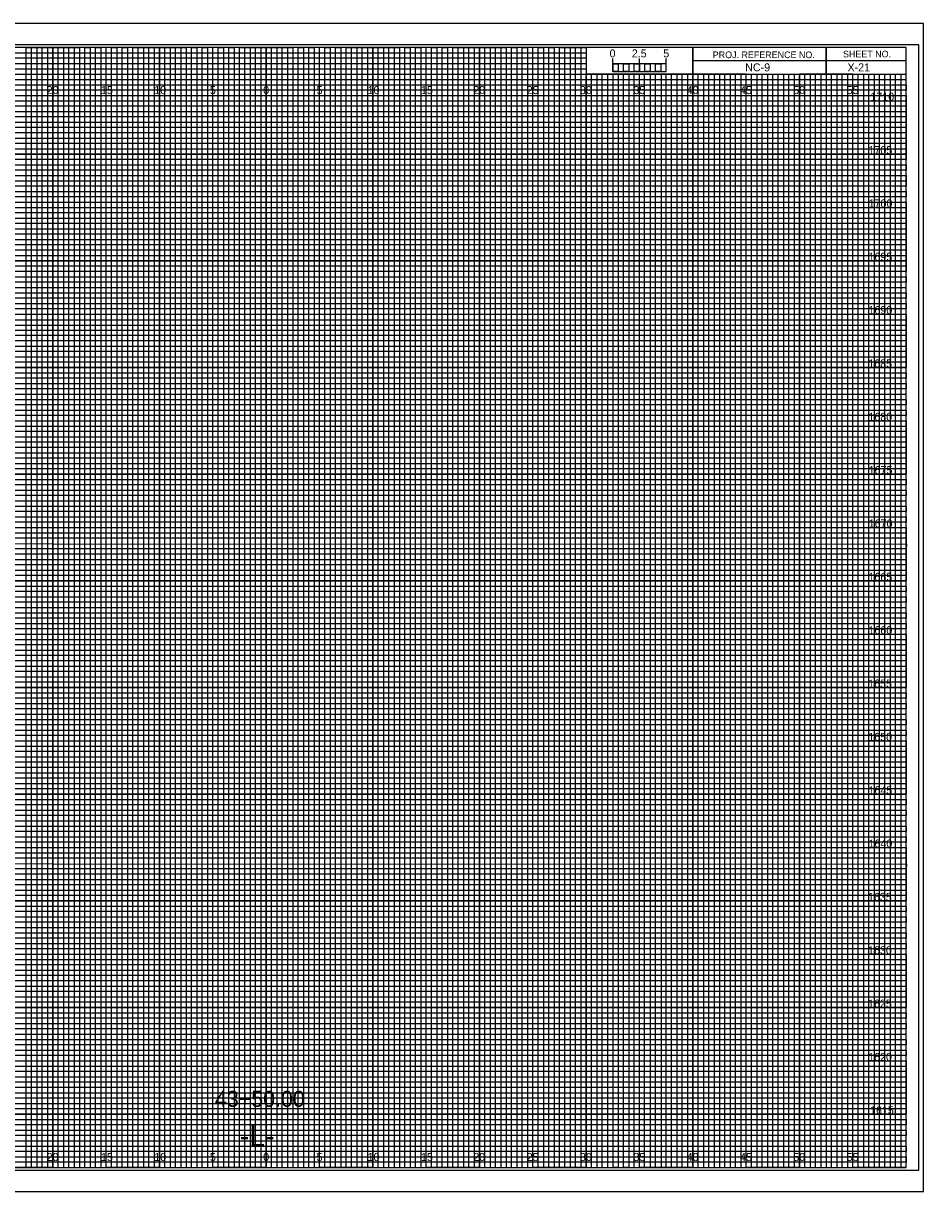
# Model space of a CAD drawing. Extents: x -8289 to 162, y -2 to 23207.
# Drawn here: x 77.2 to 161.7, y 2087.8 to 2197.2 of the extents above; entities that cross this region are included whole.
import ezdxf

# ---------------------------------------------------------------- set-up
doc = ezdxf.new("R2010")
doc.units = 0
for name, color, linetype in [('Prop XS Alignment Label', 7, 'Continuous'), ('Prop XS Bar Scale Labels', 7, 'Continuous'), ('Prop XS Elevation Labels', 7, 'Continuous'), ('Prop XS Offset Labels', 7, 'Continuous'), ('Prop XS Project Number', 7, 'Continuous'), ('Prop XS Sheet Number', 7, 'Continuous'), ('Prop XS Station Labels', 7, 'Continuous'), ('Sheet Cross Section CELL', 7, 'Continuous'), ('Sheet Cross Section Grid Major CELL', 7, 'Continuous'), ('Sheet Cross Section Grid Middle CELL', 7, 'Continuous'), ('Sheet Cross Section Grid Minor 1 CELL', 7, 'Continuous'), ('Sheet Cross Section Grid Minor 2 CELL', 7, 'Continuous'), ('Sheet Cross Section Scale CELL', 7, 'Continuous'), ('Sheet Cutting Line CELL', 7, 'Continuous'), ('Sheet DOT Grid CELL', 7, 'Continuous'), ('Sheet Plot Border Inside CELL', 7, 'Continuous'), ('Sheet Plot Border Outside CELL', 7, 'Continuous')]:
    doc.layers.add(name, color=color, linetype=linetype)

msp = doc.modelspace()

# ---------------------------------------------------------------- linework, layer by layer
at = {"layer": 'Sheet Cross Section CELL'}
for p, q in [((152.5, 2195), (152.5, 2192.5)), ((152.5, 2192.5), (152.5, 2195)), ((140, 2193.75), (140, 2192.5)), ((160, 2193.74), (140, 2193.74)), ((140, 2192.5), (160, 2192.5))]:
    msp.add_line(p, q, dxfattribs=at)
for points in [[(160, 2195), (0, 2195), (0, 2090), (160, 2090)], [(140, 2195), (130, 2195), (130, 2192.51), (140, 2192.51)], [(160, 2195), (140, 2195), (140, 2192.5), (160, 2192.5)]]:
    msp.add_lwpolyline(points, close=True, dxfattribs=at)
at = {"layer": 'Sheet Cross Section Grid Major CELL'}
for p, q in [((85, 2195), (80, 2195)), ((80, 2195), (80, 2090)), ((85, 2090), (85, 2195)), ((95, 2195), (90, 2195)), ((90, 2195), (90, 2090)), ((95, 2090), (95, 2195)), ((105, 2195), (100, 2195)), ((100, 2195), (100, 2090)), ((105, 2090), (105, 2195)), ((115, 2195), (110, 2195)), ((110, 2195), (110, 2090)), ((115, 2090), (115, 2195)), ((125, 2195), (120, 2195)), ((120, 2195), (120, 2090)), ((125, 2090), (125, 2195)), ((130, 2195), (130, 2090)), ((135, 2090), (135, 2192.5)), ((145, 2192.5), (140, 2192.5)), ((140, 2192.5), (140, 2090)), ((145, 2090), (145, 2192.5)), ((155, 2192.5), (150, 2192.5)), ((150, 2192.5), (150, 2090)), ((155, 2090), (155, 2192.5)), ((80, 2090), (75, 2090)), ((90, 2090), (85, 2090)), ((100, 2090), (95, 2090)), ((110, 2090), (105, 2090)), ((120, 2090), (115, 2090)), ((130, 2090), (125, 2090)), ((140, 2090), (135, 2090)), ((150, 2090), (145, 2090)), ((160, 2090), (155, 2090)), ((160, 2090), (160, 2090))]:
    msp.add_line(p, q, dxfattribs=at)
for points in [[(0, 2190), (160, 2190), (160, 2185), (0, 2185)], [(0, 2180), (160, 2180), (160, 2175), (0, 2175)], [(0, 2170), (160, 2170), (160, 2165), (0, 2165)], [(0, 2160), (160, 2160), (160, 2155), (0, 2155)], [(0, 2150), (160, 2150), (160, 2145), (0, 2145)], [(0, 2140), (160, 2140), (160, 2135), (0, 2135)], [(0, 2130), (160, 2130), (160, 2125), (0, 2125)], [(0, 2120), (160, 2120), (160, 2115), (0, 2115)], [(0, 2110), (160, 2110), (160, 2105), (0, 2105)], [(0, 2100), (160, 2100), (160, 2095), (0, 2095)]]:
    msp.add_lwpolyline(points, dxfattribs=at)
at = {"layer": 'Sheet Cross Section Grid Middle CELL'}
for points in [[(72.5, 2090), (77.5, 2090), (77.5, 2195), (82.5, 2195), (82.5, 2090), (87.5, 2090), (87.5, 2195), (92.5, 2195), (92.5, 2090), (97.5, 2090), (97.5, 2195), (102.5, 2195), (102.5, 2090), (107.5, 2090), (107.5, 2195), (112.5, 2195), (112.5, 2090), (117.5, 2090), (117.5, 2195), (122.5, 2195), (122.5, 2090), (127.5, 2090), (127.5, 2195), (129.97, 2195), (130, 2195), (130, 2192.5), (132.5, 2192.5), (132.5, 2090), (137.5, 2090), (137.5, 2192.5), (142.5, 2192.5), (142.5, 2090), (147.5, 2090), (147.5, 2192.5), (152.5, 2192.5), (152.5, 2090), (157.5, 2090), (157.5, 2192.5)], [(0, 2192.5), (137.5, 2192.5)], [(0, 2182.5), (160, 2182.5), (160, 2187.5), (0, 2187.5)], [(0, 2172.5), (160, 2172.5), (160, 2177.5), (0, 2177.5)], [(0, 2162.5), (160, 2162.5), (160, 2167.5), (0, 2167.5)], [(0, 2152.5), (160, 2152.5), (160, 2157.5), (0, 2157.5)], [(0, 2142.5), (160, 2142.5), (160, 2147.5), (0, 2147.5)], [(0, 2132.5), (160, 2132.5), (160, 2137.5), (0, 2137.5)], [(0, 2122.5), (160, 2122.5), (160, 2127.5), (0, 2127.5)], [(0, 2112.5), (160, 2112.5), (160, 2117.5), (0, 2117.5)], [(0, 2102.5), (160, 2102.5), (160, 2107.5), (0, 2107.5)], [(0, 2092.5), (160, 2092.5), (160, 2097.5), (0, 2097.5)]]:
    msp.add_lwpolyline(points, dxfattribs=at)
at = {"layer": 'Sheet Cross Section Grid Minor 1 CELL'}
for p, q in [((0, 2194.5), (130, 2194.5)), ((130, 2194.5), (130, 2193.99)), ((130, 2193.99), (0, 2193.99)), ((0, 2193.5), (130, 2193.5)), ((130, 2193.5), (130, 2192.95)), ((130, 2192.95), (0, 2192.95)), ((0, 2192), (160, 2192))]:
    msp.add_line(p, q, dxfattribs=at)
for points in [[(0, 2191.5), (135, 2191.5), (160, 2191.5), (160, 2191), (0, 2191)], [(0, 2190.5), (160, 2190.5), (160, 2189.5), (0, 2189.5)], [(0, 2189), (160, 2189), (160, 2188.5), (0, 2188.49)], [(0, 2188), (160, 2188), (160, 2187), (0, 2187)], [(0, 2186.5), (160, 2186.5), (160, 2186), (0, 2186)], [(0, 2185.5), (160, 2185.5), (160, 2184.5), (0, 2184.5)], [(0, 2184), (160, 2184), (160, 2183.5), (0, 2183.5)], [(0, 2183), (160, 2183), (160, 2182), (0, 2182)], [(0, 2181.5), (160, 2181.5), (160, 2181), (0, 2181)], [(0, 2180.5), (160, 2180.5), (160, 2179.5), (0, 2179.5)], [(0, 2179), (160, 2179), (160, 2178.5), (0, 2178.5)], [(0, 2178), (160, 2178), (160, 2176.97), (160, 2176.5), (160, 2176), (0, 2176)], [(0, 2177), (160, 2177), (160, 2176.5), (0, 2176.5)], [(0, 2175.5), (160, 2175.5), (160, 2174.5), (0, 2174.51)], [(0, 2174.51), (160, 2174.5), (160, 2174), (0, 2174)], [(0, 2173.5), (160, 2173.5), (160, 2173), (0, 2173)], [(0, 2172), (160, 2172), (160, 2171.5), (0, 2171.5)], [(0, 2171), (160, 2171), (160, 2170.5), (0, 2170.5)], [(-0.04, 2169.45), (160, 2169.45), (160, 2168.94), (-0.04, 2168.94)], [(0, 2168.5), (160, 2168.5), (160, 2168), (0, 2168)], [(0, 2167), (160, 2167), (160, 2166.5), (0, 2166.5)], [(0, 2166), (160, 2166), (160, 2165.5), (0, 2165.5)], [(0, 2164.5), (160, 2164.5), (160, 2164), (0, 2164)], [(0, 2163.5), (160, 2163.5), (160, 2163), (0, 2163)], [(0, 2162), (160, 2162), (160, 2161.5), (0, 2161.5)], [(0, 2161), (160, 2161), (160, 2160.5), (0, 2160.5)], [(0, 2159.5), (160, 2159.5), (160, 2158.99), (0, 2159)], [(0, 2158.5), (160, 2158.5), (160, 2158), (0, 2158)], [(0, 2157), (160, 2157), (160, 2156.5), (0, 2156.5)], [(0, 2156), (160, 2156), (160, 2155.5), (0, 2155.5)], [(0, 2154.5), (160, 2154.5), (160, 2154), (0, 2154)], [(0, 2153.5), (160, 2153.5), (160, 2153), (0, 2153)], [(0, 2152), (160, 2152), (160, 2151.5), (0, 2151.5)], [(0, 2151), (160, 2151), (160, 2150.5), (0, 2150.5)], [(0, 2149.5), (160, 2149.5), (160, 2149), (0, 2149)], [(0, 2148.49), (160.03, 2148.45), (160, 2148), (0, 2148)], [(0, 2147), (160, 2147), (160, 2146.5), (0, 2146.5)], [(0, 2146), (160, 2146), (160, 2145.5), (0, 2145.5)], [(0, 2144.5), (160, 2144.5), (160, 2144), (0, 2144)], [(0, 2143.5), (160, 2143.5), (160, 2143), (0, 2143)], [(0, 2142), (160, 2142), (160, 2141.5), (0, 2141.5)], [(0, 2141), (160, 2141), (160, 2140.5), (0, 2140.5)], [(0, 2139.5), (160, 2139.5), (160, 2139), (0, 2139)], [(0, 2138.5), (160, 2138.5), (160, 2138), (0, 2138)], [(0, 2137), (160, 2137), (160, 2136.5), (0, 2136.5)], [(0, 2136), (160, 2136), (160, 2135.5), (0, 2135.5)], [(0, 2134.5), (160, 2134.5), (160, 2134), (0, 2134)], [(0, 2133.5), (160, 2133.5), (160, 2133), (0, 2133)], [(0, 2132), (160, 2132), (160, 2131.5), (0, 2131.5)], [(0, 2131), (160, 2131), (160, 2130.5), (0, 2130.5)], [(0, 2129.5), (160, 2129.5), (160, 2128.99), (0, 2129)], [(0, 2128.5), (160, 2128.5), (160, 2128), (0, 2128)], [(0, 2127), (160, 2127), (160, 2126.5), (0, 2126.5)], [(0, 2126), (160, 2126), (160, 2125.5), (0, 2125.5)], [(0, 2124.5), (160, 2124.5), (160, 2124), (0, 2124)], [(0, 2123.5), (160, 2123.5), (160, 2123), (0, 2123)], [(0, 2122), (160, 2122), (160, 2121.5), (0, 2121.5)], [(0, 2121), (160, 2121), (160, 2120.5), (0, 2120.5)], [(0, 2119.5), (160, 2119.5), (160, 2119), (0, 2119)], [(0, 2118.49), (160.03, 2118.45), (160, 2118), (0, 2118)], [(0, 2117), (160, 2117), (160, 2116.5), (0, 2116.5)], [(0, 2116), (160, 2116), (160, 2115.5), (0, 2115.5)], [(0, 2114.5), (160, 2114.5), (160, 2114), (0, 2114)], [(0, 2113.5), (160, 2113.5), (160, 2113), (0, 2113)], [(0, 2112), (160, 2112), (160, 2111.5), (0, 2111.5)], [(0, 2111), (160, 2111), (160, 2110.5), (0, 2110.5)], [(0, 2109.5), (160, 2109.5), (160, 2109), (0, 2109)], [(0, 2108.5), (160, 2108.5), (160, 2108), (0, 2108)], [(0, 2107), (160, 2107), (160, 2106.5), (0, 2106.5)], [(0, 2106), (160, 2106), (160, 2105.5), (0, 2105.5)], [(0, 2104.5), (160, 2104.5), (160, 2104), (0, 2104)], [(0, 2103.5), (160, 2103.5), (160, 2103), (0, 2103)], [(0, 2102), (160, 2102), (160, 2101.5), (0, 2101.5)], [(0, 2101), (160, 2101), (160, 2100.5), (0, 2100.5)], [(0, 2099.5), (160, 2099.5), (160, 2099), (0, 2099)], [(0, 2098.5), (160, 2098.5), (160, 2098), (0, 2098)], [(0, 2097), (160, 2097), (160, 2096.5), (0, 2096.5)], [(0, 2096), (160, 2096), (160, 2095.5), (0, 2095.5)], [(0, 2094.5), (160, 2094.5), (160, 2094), (0, 2094)], [(0, 2093.5), (160, 2093.5), (160, 2093), (0, 2093)], [(0, 2092), (160, 2092), (160, 2091.5), (0, 2091.5)], [(0, 2091), (160, 2091), (160, 2090.5), (0, 2090.5)]]:
    msp.add_lwpolyline(points, dxfattribs=at)
at = {"layer": 'Sheet Cross Section Grid Minor 2 CELL'}
for p, q in [((133.5, 2192.5), (133, 2192.5)), ((133, 2192.5), (133, 2090)), ((133.5, 2090), (133.5, 2192.5)), ((134.5, 2192.5), (134, 2192.5)), ((134, 2192.5), (134, 2090)), ((134.5, 2090), (134.5, 2192.5)), ((133, 2090), (132.5, 2090)), ((134, 2090), (133.5, 2090))]:
    msp.add_line(p, q, dxfattribs=at)
for points in [[(77.5, 2090), (78, 2090), (78, 2195), (78.5, 2195), (78.5, 2090)], [(78.5, 2090), (79, 2090), (79, 2195), (79.5, 2195), (79.5, 2090)], [(80, 2090), (80.5, 2090), (80.5, 2195), (81, 2195), (81, 2090)], [(81, 2090), (81.5, 2090), (81.5, 2195), (82, 2195), (82, 2090)], [(82.5, 2090), (83, 2090), (83, 2195), (83.5, 2195), (83.5, 2090)], [(83.5, 2090), (84, 2090), (84, 2195), (84.5, 2195), (84.5, 2090)], [(85, 2090), (85.5, 2090), (85.5, 2195), (86, 2195), (86, 2090)], [(86, 2090), (86.5, 2090), (86.5, 2195), (87, 2195), (87, 2090)], [(87.5, 2090), (88, 2090), (88, 2195), (88.5, 2195), (88.5, 2090)], [(88.5, 2090), (89, 2090), (89, 2195), (89.5, 2195), (89.5, 2090)], [(90, 2090), (90.5, 2090), (90.5, 2195), (91, 2195), (91, 2090)], [(91, 2090), (91.5, 2090), (91.5, 2195), (92, 2195), (92, 2090)], [(92.5, 2090), (93, 2090), (93, 2195), (93.5, 2195), (93.5, 2090)], [(93.5, 2090), (94, 2090), (94, 2195), (94.5, 2195), (94.5, 2090)], [(95, 2090), (95.5, 2090), (95.5, 2195), (96, 2195), (96, 2090)], [(96, 2090), (96.5, 2090), (96.5, 2195), (97, 2195), (97, 2090)], [(97.5, 2090), (98, 2090), (98, 2195), (98.5, 2195), (98.5, 2090)], [(98.5, 2090), (99, 2090), (99, 2195), (99.5, 2195), (99.5, 2090)], [(100, 2090), (100.5, 2090), (100.5, 2195), (101, 2195), (101, 2090)], [(101, 2090), (101.5, 2090), (101.5, 2195), (102, 2195), (102, 2090)], [(102.5, 2090), (103, 2090), (103, 2195), (103.5, 2195), (103.5, 2090)], [(103.5, 2090), (104, 2090), (104, 2195), (104.5, 2195), (104.5, 2090)], [(105, 2090), (105.5, 2090), (105.5, 2195), (106, 2195), (106, 2090)], [(106, 2090), (106.5, 2090), (106.5, 2195), (107, 2195), (107, 2090)], [(107.5, 2090), (108, 2090), (108, 2195), (108.5, 2195), (108.5, 2090)], [(108.5, 2090), (109, 2090), (109, 2195), (109.5, 2195), (109.5, 2090)], [(110, 2090), (110.5, 2090), (110.5, 2195), (111, 2195), (111, 2090)], [(111, 2090), (111.5, 2090), (111.5, 2195), (112, 2195), (112, 2090)], [(112.5, 2090), (113, 2090), (113, 2195), (113.5, 2195), (113.5, 2090)], [(113.5, 2090), (114, 2090), (114, 2195), (114.5, 2195), (114.5, 2090)], [(115, 2090), (115.5, 2090), (115.5, 2195), (116, 2195), (116, 2090)], [(116, 2090), (116.5, 2090), (116.5, 2195), (117, 2195), (117, 2090)], [(117.5, 2090), (118, 2090), (118, 2195), (118.5, 2195), (118.5, 2090)], [(118.5, 2090), (119, 2090), (119, 2195), (119.5, 2195), (119.5, 2090)], [(120, 2090), (120.5, 2090), (120.5, 2195), (121, 2195), (121, 2090)], [(121, 2090), (121.5, 2090), (121.5, 2195), (122, 2195), (122, 2090)], [(122.5, 2090), (123, 2090), (123, 2195), (123.5, 2195), (123.5, 2090)], [(123.5, 2090), (124, 2090), (124, 2195), (124.5, 2195), (124.5, 2090)], [(125, 2090), (125.5, 2090), (125.5, 2195), (126, 2195), (126, 2090)], [(126, 2090), (126.5, 2090), (126.5, 2195), (127, 2195), (127, 2090)], [(127.5, 2090), (128, 2090), (128, 2195), (128.5, 2195), (128.5, 2090)], [(128.5, 2090), (129, 2090), (129, 2195), (129.5, 2195), (129.5, 2090)], [(130, 2090), (130.5, 2090), (130.5, 2192.5), (131.01, 2192.5), (131.01, 2090)], [(131, 2090), (131.5, 2090), (131.5, 2192.5), (132, 2192.5), (132, 2090)], [(135, 2090), (135.49, 2090), (135.49, 2192.5), (136, 2192.5), (136, 2090)], [(136, 2090), (136.5, 2090), (136.5, 2192.5), (137.03, 2192.5), (137.03, 2090)], [(137.5, 2090), (138, 2090), (138, 2192.5), (138.5, 2192.5), (138.5, 2090)], [(138.5, 2090), (139, 2090), (139, 2192.5), (139.5, 2192.5), (139.5, 2090)], [(140, 2090), (140.5, 2090), (140.5, 2192.5), (141, 2192.5), (141, 2090)], [(141, 2090), (141.5, 2090), (141.5, 2192.5), (142, 2192.5), (142, 2090)], [(142.5, 2090), (143, 2090), (143, 2192.5), (143.5, 2192.5), (143.5, 2090)], [(143.5, 2090), (144, 2090), (144, 2192.5), (144.5, 2192.5), (144.5, 2090)], [(145, 2090), (145.5, 2090), (145.5, 2192.5), (146, 2192.5), (146, 2090)], [(146, 2090), (146.5, 2090), (146.5, 2192.5), (147, 2192.5), (147, 2090)], [(147.5, 2090), (148, 2090), (148, 2192.5), (148.5, 2192.5), (148.5, 2090)], [(148.5, 2090), (149, 2090), (149, 2192.5), (149.5, 2192.5), (149.5, 2090)], [(150, 2090), (150.5, 2090), (150.5, 2192.5), (151, 2192.5), (151, 2090)], [(151, 2090), (151.5, 2090), (151.5, 2192.5), (152, 2192.5), (152, 2090)], [(152.5, 2090), (153, 2090), (153, 2192.5), (153.5, 2192.5), (153.5, 2090)], [(153.5, 2090), (154, 2090), (154, 2192.5), (154.5, 2192.5), (154.5, 2090)], [(155, 2090), (155.5, 2090), (155.5, 2192.5), (156, 2192.5), (156, 2090)], [(156, 2090), (156.5, 2090), (156.5, 2192.5), (157, 2192.5), (157, 2090)], [(157.5, 2090), (158, 2090), (158, 2192.5), (158.5, 2192.5), (158.5, 2090)], [(158.5, 2090), (159, 2090), (159, 2192.5), (159.5, 2192.5), (159.5, 2090)]]:
    msp.add_lwpolyline(points, dxfattribs=at)
at = {"layer": 'Sheet Cross Section Scale CELL'}
for p, q in [((132.5, 2192.74), (132.5, 2193.95)), ((132.5, 2193.45), (132.5, 2193.95)), ((135, 2192.74), (135, 2193.95)), ((137.5, 2192.74), (137.5, 2193.95)), ((137.5, 2193.45), (137.5, 2193.95))]:
    msp.add_line(p, q, dxfattribs=at)
for points in [[(137.5, 2193.45), (132.5, 2193.45), (132.5, 2192.74), (137.5, 2192.74)], [(132.5, 2193.45), (133, 2193.45), (133, 2192.74), (132.5, 2192.74)], [(133.5, 2193.45), (134, 2193.45), (134, 2192.74), (133.5, 2192.74)], [(134.5, 2193.45), (135, 2193.45), (135, 2192.74), (134.5, 2192.74)], [(135.5, 2193.45), (136, 2193.45), (136, 2192.74), (135.5, 2192.74)], [(136.5, 2193.45), (137, 2193.45), (137, 2192.74), (136.5, 2192.74)]]:
    msp.add_lwpolyline(points, close=True, dxfattribs=at)
at = {"layer": 'Sheet Cutting Line CELL'}
for p, q in [((161.65, 2197.25), (-6.7, 2197.25)), ((-6.7, 2087.75), (161.65, 2087.75))]:
    msp.add_line(p, q, dxfattribs=at)
at = {"layer": 'Sheet DOT Grid CELL'}
for p, q in [((80, 2090), (80, 2195)), ((85, 2090), (85, 2195)), ((90, 2090), (90, 2195)), ((95, 2090), (95, 2195)), ((100, 2090), (100, 2195)), ((105, 2090), (105, 2195)), ((110, 2090), (110, 2195)), ((115, 2090), (115, 2195)), ((120, 2090), (120, 2195)), ((125, 2090), (125, 2195)), ((130, 2090), (130, 2192.34)), ((135, 2090), (135, 2192.34)), ((140, 2090), (140, 2192.34)), ((145, 2090), (145, 2192.34)), ((150, 2090), (150, 2192.34)), ((155, 2090), (155, 2192.34)), ((0, 2190), (160, 2190)), ((0, 2185), (160, 2185)), ((0, 2180), (160, 2180)), ((0, 2175), (160, 2175)), ((0, 2170), (160, 2170)), ((0, 2165), (160, 2165)), ((0, 2160), (160, 2160)), ((0, 2155), (160, 2155)), ((0, 2150), (160, 2150)), ((0, 2145), (160, 2145)), ((0, 2140), (160, 2140)), ((0, 2135), (160, 2135)), ((0, 2130), (160, 2130)), ((0, 2125), (160, 2125)), ((0, 2120), (160, 2120)), ((0, 2115), (160, 2115)), ((0, 2110), (160, 2110)), ((0, 2105), (160, 2105)), ((0, 2100), (160, 2100)), ((0, 2095), (160, 2095))]:
    msp.add_line(p, q, dxfattribs=at)
at = {"layer": 'Sheet Plot Border Inside CELL'}
msp.add_lwpolyline([(-5.4, 2089.75), (161.2, 2089.75), (161.2, 2195.25), (-5.4, 2195.25)], close=True, dxfattribs=at)
at = {"layer": 'Sheet Plot Border Outside CELL'}
msp.add_lwpolyline([(-6.7, 2087.75), (161.65, 2087.75), (161.65, 2197.25), (-6.7, 2197.25)], close=True, dxfattribs=at)

# ---------------------------------------------------------------- texts
at = {"layer": 'Prop XS Alignment Label'}
msp.add_text('-L-', height=2, dxfattribs=at).set_placement((97.53, 2092))
at = {"layer": 'Prop XS Bar Scale Labels'}
for s, p in [('2.5', (134.29, 2194.06)), ('5', (137.24, 2194.06))]:
    msp.add_text(s, height=0.75, dxfattribs=at).set_placement(p)
at = {"layer": 'Prop XS Elevation Labels'}
for s, p in [('1710', (156.66, 2190)), ('1705', (156.48, 2185)), ('1700', (156.49, 2180)), ('1695', (156.48, 2175)), ('1690', (156.48, 2170)), ('1685', (156.46, 2165)), ('1680', (156.47, 2160)), ('1675', (156.49, 2155)), ('1670', (156.5, 2150)), ('1665', (156.48, 2145)), ('1660', (156.48, 2140)), ('1655', (156.45, 2135)), ('1650', (156.46, 2130)), ('1645', (156.48, 2125)), ('1640', (156.48, 2120)), ('1635', (156.43, 2115)), ('1630', (156.44, 2110)), ('1625', (156.44, 2105)), ('1620', (156.45, 2100)), ('1615', (156.63, 2095))]:
    msp.add_text(s, height=0.75, dxfattribs=at).set_placement(p)
at = {"layer": 'Prop XS Offset Labels'}
for s, p in [('20', (79.43, 2190.62)), ('15', (84.53, 2190.62)), ('10', (89.52, 2190.62)), ('5', (94.74, 2190.62)), ('0', (99.73, 2190.62)), ('0', (99.73, 2190.62)), ('5', (104.74, 2190.62)), ('10', (109.52, 2190.62)), ('15', (114.53, 2190.62)), ('20', (119.43, 2190.62)), ('25', (124.44, 2190.62)), ('30', (129.43, 2190.62)), ('35', (134.44, 2190.62)), ('40', (139.43, 2190.62)), ('45', (144.44, 2190.62)), ('50', (149.43, 2190.62)), ('55', (154.44, 2190.62)), ('20', (79.43, 2090.62)), ('15', (84.53, 2090.62)), ('10', (89.52, 2090.62)), ('5', (94.74, 2090.62)), ('0', (99.73, 2090.62)), ('0', (99.73, 2090.62)), ('5', (104.74, 2090.62)), ('10', (109.52, 2090.62)), ('15', (114.53, 2090.62)), ('20', (119.43, 2090.62)), ('25', (124.44, 2090.62)), ('30', (129.43, 2090.62)), ('35', (134.44, 2090.62)), ('40', (139.43, 2090.62)), ('45', (144.44, 2090.62)), ('50', (149.43, 2090.62)), ('55', (154.44, 2090.62))]:
    msp.add_text(s, height=0.75, dxfattribs=at).set_placement(p)
at = {"layer": 'Prop XS Project Number'}
msp.add_text('NC-9', height=0.75, dxfattribs=at).set_placement((144.92, 2192.75))
at = {"layer": 'Prop XS Sheet Number'}
msp.add_text('X-21', height=0.75, dxfattribs=at).set_placement((154.51, 2192.75))
at = {"layer": 'Prop XS Station Labels'}
msp.add_text('43+50.00', height=1.5, dxfattribs=at).set_placement((95.21, 2095.7))
at = {"layer": 'Sheet Cross Section CELL'}
for s, p in [('PROJ. REFERENCE NO.', (141.88, 2193.99)), ('SHEET NO.', (154.09, 2194.06))]:
    msp.add_text(s, height=0.625, dxfattribs=at).set_placement(p)
at = {"layer": 'Sheet Cross Section Scale CELL'}
msp.add_text('0', height=0.75, dxfattribs=at).set_placement((132.21, 2194.06))

doc.saveas('drawing.dxf')
